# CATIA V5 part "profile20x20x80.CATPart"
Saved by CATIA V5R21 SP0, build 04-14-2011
Part number: 80
Bounding box of the stored display mesh (mm): x -24.289 to -4.289, y -1.335 to 18.665, z 0 to 80
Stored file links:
  C:\Users\2027.DESARCY-LEMIE30\Desktop\V16(05.04.2023)\profile20x20x80.CATPart
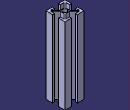
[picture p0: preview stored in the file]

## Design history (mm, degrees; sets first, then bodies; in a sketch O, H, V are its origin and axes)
Body1 (main body)
  Sketch1 on xy-plane, origin (0, 0, 0), H (1, 0, 0), V (0, 1, 0)
    point P1 (-17.2892, 11.6647)
    line L1 (-16.2892, 11.6647) -> (-12.2892, 11.6647)
    point P2 (-11.2892, 11.6647)
    line L2 (-11.2892, 10.6647) -> (-11.2892, 6.6647)
    point P3 (-11.2892, 5.6647)
    line L3 (-12.2892, 5.6647) -> (-16.2892, 5.6647)
    point P4 (-17.2892, 5.6647)
    line L4 (-17.2892, 6.6647) -> (-17.2892, 10.6647)
    point P5 (-24.2892, 18.6647)
    point P6 (-4.2892, 18.6647)
    point P7 (-4.2892, -1.3353)
    line L5 (-11.1892, 18.6647) -> (-11.1892, 16.6647)
    point P8 (-11.1892, 18.6647)
    point P10 (-11.1892, 18.6647)
    point P11 (-17.3892, 18.6647)
    line L6 (-17.3892, 18.6647) -> (-17.3892, 16.6647)
    point P12 (-17.3892, 18.6647)
    line L7 (-11.1892, 18.6647) -> (-4.2892, 18.6647)
    point P14 (-11.1892, 18.6647)
    point P15 (-4.2892, 18.6647)
    point P16 (-11.1892, -1.3353)
    point P17 (-17.3892, -1.3353)
    line L8 (-17.3892, -1.3353) -> (-17.3892, 0.6647)
    point P18 (-17.3892, -1.3353)
    line L9 (-11.1892, -1.3353) -> (-11.1892, 0.6647)
    point P20 (-11.1892, -1.3353)
    line L10 (-24.2892, -1.3353) -> (-17.3892, -1.3353)
    point P22 (-24.2892, -1.3353)
    point P23 (-17.3892, -1.3353)
    line L11 (-11.1892, -1.3353) -> (-4.2892, -1.3353)
    point P24 (-11.1892, -1.3353)
    point P25 (-4.2892, -1.3353)
    line L12 (-24.2892, 18.6647) -> (-17.3892, 18.6647)
    point P26 (-24.2892, 18.6647)
    point P27 (-17.3892, 18.6647)
    point P28 (-4.2892, 5.5647)
    point P29 (-4.2892, 11.7647)
    line L13 (-6.2892, 11.7647) -> (-4.2892, 11.7647)
    point P31 (-4.2892, 11.7647)
    line L14 (-4.2892, 5.5647) -> (-6.2892, 5.5647)
    point P32 (-4.2892, 5.5647)
    point P34 (-24.2892, 5.5647)
    point P35 (-24.2892, 11.7647)
    line L15 (-24.2892, 11.7647) -> (-22.2892, 11.7647)
    point P36 (-24.2892, 11.7647)
    line L16 (-24.2892, 5.5647) -> (-22.2892, 5.5647)
    point P38 (-24.2892, 5.5647)
    line L17 (-4.2892, 18.6647) -> (-4.2892, 11.7647)
    point P40 (-4.2892, 18.6647)
    point P41 (-4.2892, 11.7647)
    line L18 (-24.2892, 18.6647) -> (-24.2892, 11.7647)
    point P42 (-24.2892, 18.6647)
    point P43 (-24.2892, 11.7647)
    line L19 (-24.2892, -1.3353) -> (-24.2892, 5.5647)
    point P44 (-24.2892, -1.3353)
    point P45 (-24.2892, 5.5647)
    line L20 (-4.2892, -1.3353) -> (-4.2892, 5.5647)
    point P46 (-4.2892, -1.3353)
    point P47 (-4.2892, 5.5647)
    line L21 (-22.2892, 5.5647) -> (-22.2892, 1.6647)
    line L22 (-21.2892, 0.6647) -> (-17.3892, 0.6647)
    line L23 (-6.2892, 5.5647) -> (-6.2892, 1.6647)
    line L24 (-11.1892, 0.6647) -> (-7.2892, 0.6647)
    line L25 (-11.1892, 16.6647) -> (-7.2892, 16.6647)
    line L26 (-6.2892, 15.6647) -> (-6.2892, 11.7647)
    line L27 (-17.3892, 16.6647) -> (-21.2892, 16.6647)
    line L28 (-22.2892, 15.6647) -> (-22.2892, 11.7647)
    point P48 (-16.2892, 11.6647)
    point P49 (-17.2892, 10.6647)
    point P50 (-17.2892, 6.6647)
    point P52 (-11.2892, 6.6647)
    point P53 (-11.2892, 10.6647)
    point P54 (-12.2892, 11.6647)
    point P55 (-12.2892, 5.6647)
    line L29 (-16.2892, 11.6647) -> (-21.2892, 16.6647)
    line L30 (-17.2892, 10.6647) -> (-22.2892, 15.6647)
    line L31 (-12.2892, 11.6647) -> (-7.2892, 16.6647)
    line L32 (-16.2892, 5.6647) -> (-21.2892, 0.6647)
    line L33 (-17.2892, 6.6647) -> (-22.2892, 1.6647)
    line L34 (-12.2892, 5.6647) -> (-7.2892, 0.6647)
    line L35 (-11.2892, 6.6647) -> (-6.2892, 1.6647)
    line L36 (-11.2892, 10.6647) -> (-6.2892, 15.6647)
    length L5 = 2
    distance P10 P6 = 6.9
    length L6 = 2
    length L8 = 2
    length L9 = 2
    distance P7 P28 = 6.9
    distance P6 P29 = 6.9
    length L13 = 2
    length L14 = 2
    length L15 = 2
    distance P5 P42 = 0
    length L11 = 6.9
    distance P46 P7 = 0
    distance P1 P48 = 1
    distance P49 P1 = 1
    distance P4 P50 = 1
    distance P54 P2 = 1
    distance P2 P3 = 6
    distance P1 P2 = 6
    horizontal: L1 H, L3 H, L7 H, L10 H, L11 H, L12 H, L13 H, L14 H, L15 H, L16 H, L22 H, L24 H, L25 H, L27 H
    vertical: L2 V, L4 V, L5 V, L6 V, L8 V, L9 V, L17 V, L18 V, L19 V, L20 V, L21 V, L23 V, L26 V, L28 V
    coincidence: P10 P8, P11 P12, P6 P15, P8 P14, P16 L5, P17 L6, P17 P18, P16 P20, P23 L8, P24 L9, P20 P24, P27 L6, P5 P26, P29 P31, P28 P32, P34 L14, P35 L13, P34 P38, P35 P36, P40 L7, P41 L13, P6 P40, P42 L7, P43 L13, P44 L11, P45 L14, P38 P45, P46 L11, P47 L14, P49 L4, P50 L4, P52 L2, P53 L2, P55 L3, P22 P44, P25 P46
    fix: P34, P12, P5, P36, P55
  Pad1: profile Sketch1, direction (0, 0, 1), length 80
  Sketch2 on end face of Pad1, origin (0, 0, 80), H (1, 0, 0), V (0, 1, 0)
    circle A1 centre (-14.2892, 8.6647) radius 2.5
    point P1 (-14.2892, 8.6647)
    reference projected line E1 (-12.2892, 11.6647) -> (-16.2892, 11.6647) from edge [face of Pad1 from Sketch1.L1 | end face of Pad1]
    reference projected line E2 (-11.2892, 6.6647) -> (-11.2892, 10.6647) from edge [face of Pad1 from Sketch1.L2 | end face of Pad1]
    radius A1 = 2.5
    distance P1 E1 = 3
    distance P1 E2 = 3
  Pocket1: profile Sketch2, direction (0, 0, -1), length 105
